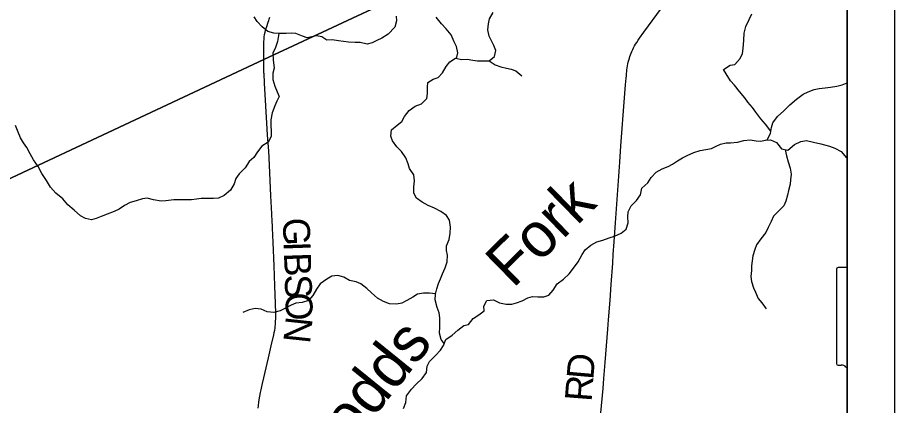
# Model space of a CAD drawing. Extents: x 0 to 34, y 0 to 22.
# Drawn here: x 7.143 to 9, y 15.305 to 16.125 of the extents above; entities that cross this region are included whole.
import ezdxf

# ---------------------------------------------------------------- set-up
doc = ezdxf.new("R2010")
doc.units = 0
for name, color, linetype in [('GM_X_Corporation_Text', 7, 'Continuous'), ('GM_X_County_Road', 7, 'Continuous'), ('GM_X_County_Road_Text', 7, 'Continuous'), ('GM_X_Minor_River', 7, 'Continuous'), ('GM_X_Minor_River_Text', 7, 'Continuous'), ('GM_X_Township_Road', 7, 'Continuous'), ('GM_X_Township_Road_Text', 7, 'Continuous'), ('SH_Data', 7, 'Continuous')]:
    doc.layers.add(name, color=color, linetype=linetype)

msp = doc.modelspace()

# ---------------------------------------------------------------- linework, layer by layer
at = {"layer": 'GM_X_Corporation_Text'}
msp.add_line((8.8775, 15.5932), (8.8775, 15.3931), dxfattribs=at)
msp.add_lwpolyline([(8.9, 15.3845), (8.9, 15.5967), (8.8807, 15.5967)], dxfattribs=at)
for centre, major_axis, start_param, end_param in [((8.8813, 15.5936), (0.00382, 0), 1.727492, 3.291633), ((8.8813, 15.3927), (0.00385, 0), 2.993084, 4.5083), ((8.8819, 15.4131), (0.0294, 0), 4.665946, 4.897461), ((8.8879, 15.3815), (0.0106, 0), 0.519207, 1.627899), ((9.0217, 15.5613), (0.2524, 0), 4.195997, 4.209216)]:
    msp.add_ellipse(centre, major_axis=major_axis, ratio=0.8, start_param=start_param, end_param=end_param, dxfattribs=at)
at = {"layer": 'GM_X_County_Road'}
msp.add_lwpolyline([(8.3784, 15.2892), (8.383, 15.3405), (8.3846, 15.3616), (8.3877, 15.3956), (8.3933, 15.4662), (8.3948, 15.486), (8.3981, 15.5274), (8.4005, 15.5603), (8.4034, 15.6055), (8.4045, 15.6241), (8.4063, 15.6508), (8.4091, 15.691), (8.4134, 15.7505), (8.4188, 15.8193), (8.421, 15.854), (8.4284, 15.9556), (8.4308, 15.9828), (8.4321, 15.9971), (8.4324, 16.0016), (8.4327, 16.0066), (8.4331, 16.0113), (8.4335, 16.0148), (8.434, 16.0186), (8.4348, 16.0228), (8.4355, 16.0271), (8.4364, 16.0309), (8.4374, 16.0349), (8.4387, 16.0391), (8.4398, 16.0426), (8.4412, 16.0461), (8.4426, 16.0501), (8.4442, 16.0536), (8.4459, 16.0574), (8.4478, 16.0612), (8.4499, 16.0651), (8.452, 16.0686), (8.4543, 16.0725), (8.4574, 16.0772), (8.4601, 16.0812), (8.4696, 16.0943), (8.5071, 16.1446)], dxfattribs=at)
at = {"layer": 'GM_X_Minor_River'}
for points in [[(8.047, 15.4358), (8.0406, 15.4442), (8.0366, 15.4575), (8.0372, 15.47), (8.0373, 15.4799), (8.0378, 15.4902), (8.0361, 15.5004), (8.0317, 15.5119), (8.0277, 15.5282), (8.0283, 15.5404), (8.0314, 15.5514), (8.035, 15.5627), (8.0386, 15.5725), (8.0433, 15.5831), (8.0491, 15.5955), (8.0527, 15.6088), (8.0537, 15.6224), (8.0519, 15.6327), (8.0513, 15.6426), (8.0575, 15.6558), (8.0596, 15.669), (8.0598, 15.6816), (8.0577, 15.6964), (8.0518, 15.7067), (8.0393, 15.7149), (8.0261, 15.7222), (8.0129, 15.7277), (8.0001, 15.7347), (7.9884, 15.7432), (7.9821, 15.7536), (7.9827, 15.7668), (7.984, 15.7801), (7.9826, 15.7927), (7.9733, 15.8057), (7.9704, 15.8156), (7.9656, 15.8282), (7.956, 15.8416), (7.9466, 15.852), (7.9373, 15.8642), (7.9336, 15.8741), (7.9353, 15.8874), (7.9472, 15.8975), (7.9572, 15.9053), (7.963, 15.9155), (7.9727, 15.9283), (7.9854, 15.9376), (7.9987, 15.9428), (8.0099, 15.954), (8.0115, 15.9646), (8.0117, 15.9779), (8.0122, 15.9878), (8.0233, 15.9948), (8.0336, 15.9985), (8.0433, 16.0082), (8.051, 16.0214), (8.0584, 16.0312), (8.0707, 16.039), (8.0839, 16.0362), (8.0957, 16.0368), (8.1071, 16.0351), (8.1169, 16.0335), (8.1302, 16.0337), (8.1416, 16.0332), (8.1531, 16.0429), (8.1563, 16.0557), (8.1519, 16.0661), (8.1471, 16.0756), (8.1419, 16.0855), (8.1391, 16.0989), (8.1408, 16.1121), (8.1428, 16.1224), (8.1506, 16.1355)], [(7.945, 16.1279), (7.9456, 16.1181), (7.9424, 16.1048), (7.9278, 16.0898), (7.9144, 16.0817), (7.904, 16.0765), (7.8945, 16.0717), (7.8834, 16.0691), (7.8687, 16.072), (7.858, 16.0725), (7.8444, 16.0731), (7.8334, 16.0744), (7.8227, 16.0756), (7.8095, 16.0781), (7.7985, 16.0775), (7.7875, 16.0844), (7.7762, 16.0865), (7.7564, 16.0822), (7.7465, 16.0857), (7.7329, 16.0916), (7.7231, 16.0921), (7.712, 16.0915), (7.698, 16.0913), (7.6862, 16.0922), (7.6734, 16.0958), (7.661, 16.1051), (7.6505, 16.1166), (7.6442, 16.1265)], [(8.0731, 16.0385), (8.0754, 16.0503), (8.0729, 16.0637), (8.0681, 16.074), (8.0614, 16.0885), (8.0506, 16.1015), (8.0412, 16.1115), (8.03, 16.1261)], [(8.7386, 15.8847), (8.727, 15.8999), (8.7173, 15.9111), (8.7068, 15.9249), (8.6994, 15.9348), (8.6893, 15.946), (8.6829, 15.9555), (8.6721, 15.9686), (8.6613, 15.982), (8.653, 15.9916), (8.6437, 16.0058), (8.6378, 16.0153), (8.652, 16.0243), (8.6619, 16.026), (8.6734, 16.0384), (8.6781, 16.049), (8.6798, 16.0596), (8.6808, 16.0774), (8.6821, 16.0918), (8.6853, 16.1062), (8.6924, 16.1209), (8.6982, 16.133)], [(7.6966, 16.0914), (7.6936, 16.0746), (7.6896, 16.0618), (7.6838, 16.0497), (7.6847, 16.036), (7.6864, 16.0178), (7.6839, 16.0072), (7.6841, 15.9939), (7.6885, 15.9802), (7.6929, 15.968), (7.697, 15.9584), (7.6926, 15.9482), (7.688, 15.9381), (7.6824, 15.9233), (7.6796, 15.9089), (7.6794, 15.8957), (7.6804, 15.8862), (7.6802, 15.8732), (7.674, 15.8612), (7.6606, 15.853), (7.6513, 15.841), (7.644, 15.8293), (7.6336, 15.8207), (7.6254, 15.8075), (7.6123, 15.7944), (7.6054, 15.7846), (7.6022, 15.7737), (7.594, 15.7601), (7.581, 15.7489), (7.5691, 15.7433), (7.5581, 15.7423), (7.5452, 15.7425), (7.5323, 15.7423), (7.5224, 15.7413), (7.5117, 15.7399), (7.5022, 15.7393), (7.4893, 15.7398), (7.4745, 15.7396), (7.4577, 15.7372), (7.4475, 15.7366), (7.4316, 15.7398), (7.4176, 15.743), (7.4077, 15.742), (7.3943, 15.7376), (7.3817, 15.734), (7.3702, 15.7273), (7.3584, 15.7199), (7.348, 15.7151), (7.3332, 15.7092), (7.3206, 15.7044), (7.3099, 15.7004), (7.3003, 15.6975), (7.2871, 15.6999), (7.2769, 15.7057), (7.2634, 15.7177), (7.2502, 15.7289), (7.239, 15.7415), (7.2244, 15.7539), (7.2131, 15.7665), (7.205, 15.7807), (7.1949, 15.7953), (7.1871, 15.8098), (7.1771, 15.8243), (7.1704, 15.8366), (7.163, 15.8503), (7.1559, 15.8599), (7.1496, 15.8706), (7.1444, 15.8825), (7.1389, 15.8966)], [(8.1416, 16.0332), (8.1544, 16.0254), (8.1669, 16.0207), (8.1786, 16.0183), (8.1885, 16.0162), (8.1983, 16.0123), (8.2111, 16.0019)], [(8.6532, 15.8603), (8.668, 15.8612), (8.681, 15.8652), (8.6943, 15.8666), (8.7072, 15.8645), (8.7167, 15.864), (8.7304, 15.8665), (8.7378, 15.8797), (8.7398, 15.8925), (8.7426, 15.9024), (8.7527, 15.9155), (8.7661, 15.9279), (8.7784, 15.9403), (8.7927, 15.9522), (8.8069, 15.963), (8.8172, 15.9678), (8.8298, 15.9726), (8.8404, 15.9751), (8.8534, 15.9765), (8.8648, 15.9779), (8.8781, 15.98), (8.8892, 15.9829), (8.9, 15.9871)], [(7.9608, 15.2983), (7.9652, 15.3112), (7.9669, 15.3248), (7.9777, 15.3395), (7.9877, 15.3496), (8.0004, 15.362), (8.0089, 15.3747), (8.011, 15.3876), (8.0153, 15.3974), (8.028, 15.4102), (8.0388, 15.4218), (8.0454, 15.4316), (8.0501, 15.4444), (8.0635, 15.4534), (8.0758, 15.4638), (8.0881, 15.4736), (8.098, 15.4761), (8.1077, 15.4885), (8.1203, 15.4967), (8.1311, 15.5045), (8.1308, 15.5148), (8.1371, 15.5268), (8.1511, 15.5278), (8.164, 15.5219), (8.178, 15.5191), (8.1898, 15.5193), (8.1997, 15.5215), (8.2115, 15.5259), (8.2241, 15.5325), (8.234, 15.5351), (8.2447, 15.5345), (8.258, 15.5348), (8.2683, 15.5377), (8.2775, 15.5489), (8.2857, 15.5621), (8.2995, 15.5718), (8.311, 15.5834), (8.3203, 15.5951), (8.3307, 15.6086), (8.3389, 15.6237), (8.3455, 15.6335), (8.357, 15.6436), (8.37, 15.6506), (8.3823, 15.6542), (8.396, 15.6594), (8.4071, 15.6626), (8.4212, 15.6693), (8.4319, 15.6775), (8.4359, 15.6911), (8.4353, 15.7033), (8.4359, 15.7139), (8.4425, 15.7271), (8.4536, 15.7383), (8.4622, 15.7504), (8.465, 15.764), (8.4781, 15.7752), (8.4847, 15.7865), (8.4955, 15.7978), (8.5081, 15.8048), (8.5207, 15.81), (8.5303, 15.8148), (8.541, 15.8222), (8.5513, 15.8282), (8.5609, 15.833), (8.5754, 15.8396), (8.5888, 15.8436), (8.6009, 15.8458), (8.6124, 15.8479), (8.6223, 15.8531), (8.6319, 15.8575), (8.6437, 15.8604), (8.6532, 15.8603)], [(8.7262, 15.8657), (8.7376, 15.8664), (8.75, 15.8605), (8.7609, 15.8475), (8.7741, 15.8443), (8.7883, 15.8566), (8.8021, 15.8633), (8.8139, 15.865), (8.8287, 15.8614), (8.8442, 15.8578), (8.8627, 15.8534), (8.8737, 15.8491), (8.8873, 15.842), (8.8985, 15.8286), (8.9, 15.8276)], [(8.7687, 15.8456), (8.7713, 15.8325), (8.7753, 15.8203), (8.7793, 15.8066), (8.781, 15.7941), (8.7801, 15.7819), (8.7789, 15.7725), (8.7756, 15.7596), (8.7736, 15.7494), (8.77, 15.7369), (8.7661, 15.7271), (8.7538, 15.7147), (8.7441, 15.705), (8.7387, 15.694), (8.7328, 15.6812), (8.7277, 15.6706), (8.7173, 15.6571), (8.708, 15.6447), (8.7041, 15.6349), (8.7005, 15.6209), (8.6988, 15.6103), (8.6975, 15.6), (8.697, 15.5898), (8.6961, 15.5777), (8.6971, 15.5666), (8.7015, 15.5537), (8.7055, 15.5441), (8.7114, 15.5312), (8.7189, 15.5216), (8.7286, 15.5089)], [(8.0283, 15.5405), (8.0157, 15.5424), (8.0032, 15.5422), (7.9899, 15.5401), (7.9803, 15.5334), (7.9673, 15.5268), (7.957, 15.5212), (7.9455, 15.5191), (7.9307, 15.5196), (7.9179, 15.5247), (7.9058, 15.5317), (7.8931, 15.5429), (7.8829, 15.5521), (7.8701, 15.5618), (7.86, 15.5661), (7.8463, 15.5689), (7.8339, 15.5759), (7.8218, 15.5795), (7.8085, 15.5782), (7.7981, 15.5715), (7.7843, 15.5621), (7.7766, 15.5509), (7.7688, 15.5373), (7.7592, 15.5268), (7.7458, 15.5228), (7.7325, 15.5214), (7.7226, 15.5166), (7.7092, 15.5096), (7.6996, 15.5048), (7.6859, 15.5012), (7.6722, 15.5029), (7.6594, 15.5083), (7.6465, 15.5096), (7.6339, 15.5072), (7.6206, 15.5013)]]:
    msp.add_lwpolyline(points, dxfattribs=at)
at = {"layer": 'GM_X_Township_Road'}
for points in [[(3.7277, 16.7873), (3.6691, 16.5264), (3.3385, 15.3189), (3.2153, 14.8228), (3.0598, 14.2522), (3.3693, 14.1947), (3.882, 14.1), (5.5061, 14.1), (5.6307, 14.246), (5.7089, 14.3412), (6.2381, 14.9624), (6.7874, 15.6255), (6.8121, 15.6375), (7.6646, 16.0363), (8.8399, 16.5839), (8.8447, 16.5834), (8.8816, 16.5789), (8.8995, 16.5764), (8.9, 16.5763), (8.9, 19.1426)], [(7.6648, 16.0357), (7.6647, 16.0593), (7.6651, 16.0743), (7.6654, 16.0789), (7.6657, 16.0836), (7.6664, 16.0892), (7.6674, 16.0942), (7.6692, 16.1008), (7.6709, 16.1062), (7.674, 16.1156), (7.6751, 16.1186), (7.6759, 16.1215), (7.6774, 16.126)], [(7.6652, 16.0075), (7.6648, 16.0326), (7.6648, 16.0357)], [(7.6526, 15.2989), (7.6534, 15.305), (7.6545, 15.3119), (7.6552, 15.3167), (7.6566, 15.3242), (7.6581, 15.3321), (7.6592, 15.3381), (7.6606, 15.3447), (7.662, 15.3515), (7.6745, 15.4054), (7.6807, 15.4307), (7.6861, 15.4542), (7.687, 15.4591), (7.688, 15.464), (7.6886, 15.4683), (7.6891, 15.4719), (7.6894, 15.4762), (7.6897, 15.4793), (7.6899, 15.4839), (7.69, 15.4873), (7.69, 15.4919), (7.69, 15.4997), (7.6895, 15.5202), (7.6882, 15.558), (7.6865, 15.6002), (7.6845, 15.6493), (7.6831, 15.6803), (7.6824, 15.698), (7.6821, 15.7051), (7.6818, 15.7103), (7.68, 15.748), (7.677, 15.8131), (7.6752, 15.8435), (7.6727, 15.8763), (7.6719, 15.89), (7.67, 15.9259), (7.6683, 15.9506), (7.6661, 15.9866), (7.6653, 16.0065), (7.6652, 16.0075)]]:
    msp.add_lwpolyline(points, dxfattribs=at)
msp.add_lwpolyline([(5.5061, 14.1), (8.9, 14.1), (8.9, 16.5763), (8.8995, 16.5764), (8.8816, 16.5789), (8.8447, 16.5834), (8.8399, 16.5839), (7.6646, 16.0363), (6.8121, 15.6375), (6.7874, 15.6255), (6.2381, 14.9624), (5.7089, 14.3412), (5.6307, 14.246)], close=True, dxfattribs=at)
at = {"layer": 'SH_Data'}
for p, q in [((9, 21), (9, 14)), ((8.9, 20.9), (8.9, 14.1))]:
    msp.add_line(p, q, dxfattribs=at)

# ---------------------------------------------------------------- texts
at = {"layer": 'GM_X_County_Road_Text'}
for s, rotation, p in [('D', 85.0285, (8.3622, 15.3581)), ('R', 85.554, (8.3586, 15.3117))]:
    msp.add_text(s, height=0.0568, rotation=rotation, dxfattribs=at).set_placement(p)
at = {"layer": 'GM_X_Minor_River_Text'}
for s, rotation, p in [('Fork', 44.4282, (8.1921, 15.5509)), ('Todds', 51.0511, (7.8034, 15.1628))]:
    msp.add_text(s, height=0.09469, rotation=rotation, dxfattribs=at).set_placement(p)
at = {"layer": 'GM_X_Township_Road_Text'}
for s, rotation, p in [('G', 271.9346, (7.7049, 15.7008)), ('I', 271.9404, (7.7066, 15.6508)), ('B', 271.9362, (7.7074, 15.6275)), ('S', 271.9428, (7.7089, 15.5809)), ('O', 271.818, (7.7102, 15.5426)), ('N', 263.8609, (7.7119, 15.4947))]:
    msp.add_text(s, height=0.0568, rotation=rotation, dxfattribs=at).set_placement(p)

doc.saveas('drawing.dxf')
